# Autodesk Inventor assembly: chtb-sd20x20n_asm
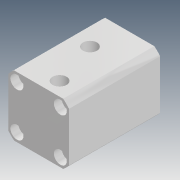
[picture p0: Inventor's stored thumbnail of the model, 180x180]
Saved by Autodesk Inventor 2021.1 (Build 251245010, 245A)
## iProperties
Company: Microsoft
Created: 2018-04
Part Number: chtb-sd20x20n_asm
Description: STEP AP214
Document SubType Name: Assembly
Designer: user
Title: chtb-sd20x20n_asm.STEP
Author: Windows
Revision Number: ÈÎºÎ
Sending System: SolidWorks 2015
Preprocessor: SwSTEP 2.0
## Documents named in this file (4)
- D:\Vault_2016\Projekty\Clamptek\Hydraulic\CHTB\CHTB-20\Inventor\CHTB-SD20x20N\chtb-sd20x20n_asm.iam
- D:\Vault_2016\Projekty\Clamptek\Hydraulic\CHTB\CHTB-20\Inventor\CHTB-SD20x20N\CHTB-SD20X20NBT.ipt
- D:\Vault_2016\Projekty\Clamptek\Hydraulic\CHTB\CHTB-20\Inventor\CHTB-SD20x20N\CHTB-SD20X20NHSG.ipt
- D:\Vault_2016\Projekty\Clamptek\Hydraulic\CHTB\CHTB-20\Inventor\CHTB-SD20x20N\QG.ipt
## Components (3 placed, 3 different names)
1. CHTB-SD20X20NBT_1
2. CHTB-SD20X20NHSG_2
3. QG_3
